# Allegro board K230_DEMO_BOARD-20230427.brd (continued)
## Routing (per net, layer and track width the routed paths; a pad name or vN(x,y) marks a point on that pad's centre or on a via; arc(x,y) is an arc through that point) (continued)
LP3_CS0: length 47.4
  TOP w0.076: v2(30.2,49.74) 29.87,50.06 U5.L3 ; v2(25.98,72.9) 25.04,73.84 U1.T20 ; R75.2 v1(31.75,46.23)
  ART03 w0.076: v2(30.2,49.74) 30.04,49.74 29.62,50.16 26.8,50.16 26.62,49.99 26.62,49.48 26.48,49.34 24.19,49.34 24.02,49.52 24.02,69.25 24.12,69.36 25.84,69.36 25.95,69.48 25.95,69.71 25.82,69.85 24.06,69.85 23.93,69.98 23.93,70.17 24.06,70.3 25.82,70.3 25.95,70.44 25.95,70.63 25.82,70.76 24.31,70.76 24.18,70.89 24.18,71.08 24.31,71.22 25.82,71.22 25.95,71.35 25.95,71.59 25.78,71.76 25.78,72.01 25.95,72.18 25.95,72.87 v2(25.98,72.9)
  ART06 w0.076: v1(31.75,46.23) 31.75,47.24 30.52,48.47 30.52,49.41 v2(30.2,49.74)
  BOTTOM w0.076: R75.2 v1(31.75,46.23)
LP3_DM0: length 32.1
  TOP w0.076: v2(32.47,74.81) 32.48,74.81 U1.D18 ; U5.L8 30.2,53.82 v2(30.2,53.74)
  ART06 w0.076: v2(32.47,74.81) 32.18,75.11 30.92,75.11 30.85,75.03 30.85,73.61 31.09,73.37 31.09,73.15 30.85,72.91 30.85,72.69 31.09,72.45 31.09,72.03 30.96,71.91 30.51,71.91 30.31,71.72 30.31,67.6 30.44,67.48 31.44,67.48 31.57,67.35 31.57,67.16 31.44,67.02 30.72,67.02 30.61,66.92 30.61,62.42 30.4,62.22 30.4,62.08 30.61,61.87 30.61,61.59 30.48,61.47 29.92,61.47 29.84,61.39 29.84,60.6 30.07,60.38 30.07,60.15 29.24,59.31 29.24,55.09 29.35,54.98 29.67,54.98 29.77,54.87 29.77,54.62 29.67,54.52 29.35,54.52 29.22,54.39 29.22,52.58 29.3,52.5 29.77,52.5 29.87,52.6 29.87,53.09 30.2,53.42 v2(30.2,53.74)
LP3_DM1: length 34.1
  TOP w0.076: v2(27.6,53.74) 27.28,54.07 U5.G8 ; U1.P17 v2(26.63,75.46)
  ART06 w0.076: v2(27.6,53.74) 27.35,53.74 27.25,53.65 27.25,52.44 27.15,52.34 26.81,52.34 26.72,52.43 26.72,54.03 26.85,54.15 27.13,54.15 27.28,54.3 27.28,59.53 27.32,59.58 27.32,62.24 28.37,63.3 28.37,65.96 28.3,66.04 26.85,66.04 26.77,66.12 26.77,71.07 26.67,71.17 26.24,71.17 26.14,71.28 26.14,72.49 26.3,72.66 26.3,73.75 26.38,73.83 27.66,73.83 27.74,73.75 27.74,73.3 27.84,73.2 28.09,73.2 28.19,73.3 28.19,74.96 28.07,75.08 27.83,75.08 27.7,74.95 27.7,74.71 27.57,74.57 27.38,74.57 27.24,74.71 27.24,75.04 26.83,75.46 v2(26.63,75.46)
LP3_DM2: length 38.6
  TOP w0.076: v2(32.15,54.54) 31.82,54.22 U5.P8 ; U1.C15 v2(33.77,76.76)
  ART06 w0.076: v2(33.77,76.76) 33.77,76.95 33.91,77.09 35.69,77.09 36.3,76.48 37.9,76.48 44.65,69.72 44.65,67.79 45.31,67.13 45.31,64.88 43.56,63.13 43.43,63.13 43.26,63.3 43.05,63.3 42.93,63.17 42.93,62.99 43.11,62.81 43.11,62.68 35.79,55.36 34.33,55.36 33.93,54.97 32.31,54.97 32.15,54.81 v2(32.15,54.54)
LP3_DM3: length 38.4
  TOP w0.076: U1.V17 v2(23.38,75.46) ; U5.D8 25.33,54.06 v2(25,53.74)
  ART06 w0.076: v2(25,53.74) 25,53.52 24.92,53.44 24.72,53.44 24.66,53.5 24.66,54.86 24.59,54.94 23.11,54.94 22.76,55.3 22.25,55.3 22.17,55.37 22.17,55.54 22.04,55.68 21.85,55.68 21.71,55.54 21.71,55.39 21.62,55.3 21.3,55.3 13.81,62.79 13.81,62.98 13.88,63.05 13.88,63.21 13.72,63.37 13.56,63.37 13.48,63.3 13.29,63.3 11.84,64.76 11.84,67.22 13.43,68.82 13.78,68.82 13.93,68.97 13.93,69.31 19.11,74.5 20.4,74.5 21.36,75.46 v2(23.38,75.46)
LP3_DQ0: length 33.3
  TOP w0.076: U5.P9 31.5,54.62 v2(31.5,54.54) ; U1.C17 v2(33.77,75.46)
  ART06 w0.076: v2(31.5,54.54) 31.17,54.21 31.17,52.66 31.27,52.56 32.52,52.56 32.61,52.65 32.61,53.21 32.49,53.34 31.9,53.34 31.82,53.42 31.82,56.44 32.72,57.33 33.02,57.33 33.15,57.45 33.15,58.29 33.83,58.98 35.37,58.98 36.14,59.75 36.14,65.76 37.06,66.67 37.06,70.03 36.22,70.87 36.22,73.76 35.93,74.05 35.93,74.41 34.88,75.46 v2(33.77,75.46)
LP3_DQ1: length 33.8
  TOP w0.076: v2(30.85,55.34) 30.85,55.27 U5.N9 ; U1.D16 v2(32.47,76.11)
  ART06 w0.076: v2(32.47,76.11) 32.7,76.11 32.8,76.01 32.8,74.63 32.66,74.49 32.25,74.49 32,74.73 31.6,74.73 31.5,74.63 31.5,71.6 31.39,71.5 30.78,71.5 30.66,71.37 30.66,70.74 30.73,70.66 31.8,70.66 31.93,70.53 31.93,70.33 31.8,70.2 30.73,70.2 30.65,70.11 30.65,69.8 30.77,69.67 31.24,69.67 31.37,69.54 31.37,69.34 31.24,69.21 30.77,69.21 30.65,69.09 30.65,68.88 30.77,68.76 31.24,68.76 31.37,68.63 31.37,68.43 31.24,68.3 30.78,68.3 30.66,68.17 30.66,67.94 30.78,67.82 31.57,67.82 31.9,67.49 31.9,66.8 31.78,66.67 31.09,66.67 30.94,66.52 30.94,61.21 30.84,61.12 30.25,61.12 30.18,61.04 30.18,60.74 30.25,60.66 30.71,60.66 30.78,60.59 30.78,60.25 29.87,59.34 29.87,55.98 30.11,55.74 30.11,54.97 30.24,54.84 30.43,54.84 30.57,54.97 30.57,55.21 30.7,55.34 v2(30.85,55.34)
LP3_DQ2: length 33.1
  TOP w0.076: U5.N10 31.17,55.67 v2(31.5,55.34) ; U1.D17 v2(33.12,76.11)
  ART06 w0.076: v2(33.12,76.11) 33.12,75.33 33.33,75.13 34.8,75.13 35.65,74.28 35.65,73.98 35.89,73.74 35.89,70.69 36.73,69.85 36.73,69.58 36.6,69.46 36.07,69.46 35.94,69.33 35.94,69.13 36.07,69 36.6,69 36.73,68.87 36.73,68.67 36.6,68.54 35.89,68.54 35.79,68.44 35.79,68.19 35.89,68.09 36.6,68.09 36.73,67.96 36.73,67.76 36.6,67.63 35.92,67.63 35.81,67.53 35.81,67.27 35.92,67.17 36.6,67.17 36.73,67.04 36.73,66.83 36.63,66.73 35.92,66.73 35.81,66.63 35.81,59.89 35.23,59.31 34.16,59.31 34.04,59.44 34.04,59.69 33.92,59.8 33.68,59.8 33.58,59.7 33.58,59.44 33.45,59.31 33.1,59.31 32.47,58.69 32.47,57.45 31.5,56.48 v2(31.5,55.34)
LP3_DQ3: length 31.9
  TOP w0.076: U1.C18 33.13,74.81 v2(33.12,74.81) ; v2(31.5,56.94) 31.5,56.87 U5.N11
  ART06 w0.076: v2(31.5,56.94) 31.5,57.2 32.14,57.85 32.14,58.85 33.46,60.17 34.34,60.17 34.42,60.1 34.42,59.72 34.49,59.64 34.8,59.64 34.87,59.72 34.87,60.09 34.95,60.17 35.38,60.17 35.46,60.25 35.46,61.45 35.38,61.53 34.01,61.53 33.88,61.65 33.88,61.86 34.01,61.98 35.33,61.98 35.46,62.11 35.46,62.31 35.33,62.44 34,62.44 33.88,62.56 33.88,62.87 33.99,62.97 35.38,62.97 35.46,63.04 35.46,63.32 35.32,63.45 34.98,63.45 34.9,63.53 34.9,63.83 34.98,63.91 35.32,63.91 35.46,64.04 35.46,68.66 35.56,68.76 35.56,69.62 35.69,69.76 35.88,69.76 36.02,69.89 36.02,70.08 35.88,70.21 35.69,70.21 35.56,70.35 35.56,73.69 35.28,73.96 35.28,74.23 35.01,74.5 33.2,74.5 33.12,74.57 v2(33.12,74.81)
LP3_DQ4: length 33.8
  TOP w0.076: U1.E18 v2(32.47,75.46) ; U5.M8 30.52,53.51 30.35,53.34 28.65,53.34 v2(28.25,52.94)
  ART06 w0.076: v2(32.47,75.46) 32.47,75.68 32.37,75.79 30.96,75.79 30.86,75.89 30.86,76.66 30.76,76.76 29.72,76.76 29.62,76.66 29.62,76.42 29.75,76.28 30.02,76.28 30.15,76.15 30.15,75.96 30.02,75.83 29.8,75.83 29.67,75.69 29.67,73.48 30.18,72.97 30.18,72.64 29.65,72.12 29.65,67.2 29.95,66.9 29.95,62.7 29.17,61.93 29.17,60.06 28.7,59.59 28.7,55.96 28.5,55.75 28.07,55.75 27.93,55.61 27.93,53.58 28.25,53.26 v2(28.25,52.94)
LP3_DQ5: length 33
  TOP w0.076: v2(30.85,54.54) 30.52,54.87 U5.M9 ; U1.E17 v2(31.82,75.46)
  ART06 w0.076: v2(30.85,54.54) 30.64,54.54 30.53,54.43 30.53,51.82 30.45,51.74 28.68,51.74 28.57,51.84 28.57,55.24 28.97,55.64 28.97,59.42 29.51,59.97 29.51,61.8 30.28,62.56 30.28,67.06 29.98,67.35 29.98,71.95 30.53,72.49 30.53,73.46 30.43,73.56 30.2,73.56 30.02,73.74 30.02,74.22 30.35,74.55 30.35,74.73 30.02,75.06 30.02,75.36 30.12,75.46 v2(31.82,75.46)
LP3_DQ6: length 30.5
  TOP w0.076: v2(30.85,56.14) 30.85,56.07 U5.M10 ; U1.B19 v2(34.42,74.16)
  ART06 w0.076: v2(30.85,56.14) 31.1,56.14 31.17,56.22 31.17,58 31.32,58.14 31.74,58.14 31.81,58.22 31.81,58.98 32.82,59.98 32.82,60.43 32.9,60.51 35.01,60.51 35.13,60.63 35.13,60.86 35,60.99 32.92,60.99 32.82,61.09 32.82,61.34 32.92,61.44 33.45,61.44 33.55,61.54 33.55,61.85 33.4,62 33.4,62.26 33.55,62.41 33.55,63.2 33.68,63.33 34.47,63.33 34.57,63.43 34.57,63.68 34.29,63.96 34.01,63.96 33.84,63.78 33.62,63.78 33.5,63.91 33.5,64.72 33.6,64.82 34.44,64.82 34.54,64.72 34.54,64.36 34.65,64.26 35.03,64.26 35.13,64.36 35.13,68.81 35.23,68.91 35.23,73.56 35,73.79 35,74.09 34.87,74.22 34.48,74.22 v2(34.42,74.16)
LP3_DQ7: length 30.7
  TOP w0.076: U5.M11 30.85,56.87 v2(30.85,56.94) ; U1.C19 v2(33.77,74.16)
  ART06 w0.076: v2(30.85,56.94) 30.85,58.49 32.49,60.12 32.49,62.36 32.61,62.49 33.07,62.49 33.2,62.61 33.2,62.82 33.07,62.94 32.61,62.94 32.49,63.07 32.49,63.27 32.61,63.4 33.07,63.4 33.2,63.53 33.2,63.73 33.07,63.86 32.61,63.86 32.49,63.99 32.49,65 32.64,65.15 34.7,65.15 34.8,65.25 34.8,65.45 34.7,65.55 33.94,65.55 33.86,65.63 33.86,68.43 33.99,68.55 34.19,68.55 34.32,68.43 34.32,66.13 34.45,66.01 34.71,66.01 34.8,66.09 34.8,69.16 34.9,69.27 34.9,73.53 34.59,73.84 34.1,73.84 v2(33.77,74.16)
LP3_DQ8: length 33.6
  TOP w0.076: U5.F11 26.95,56.87 v2(26.95,57.74) ; U1.R18 v2(25.98,75.46)
  ART06 w0.076: v2(25.98,75.46) 25.98,74.72 25.65,74.39 25.65,72.62 25.7,72.57 25.7,70.94 25.83,70.82 26.31,70.82 26.44,70.69 26.44,70.48 26.34,70.38 25.83,70.38 25.7,70.26 25.7,70.05 25.83,69.93 26.31,69.93 26.42,69.82 26.42,69.57 26.31,69.47 25.83,69.47 25.7,69.34 25.7,69.14 25.83,69.01 26.29,69.01 26.42,68.89 26.42,68.68 26.29,68.55 25.81,68.55 25.7,68.45 25.7,68.2 25.81,68.09 26.29,68.09 26.42,67.97 26.42,65.8 26.55,65.67 27.91,65.67 28.04,65.54 28.04,65.35 27.91,65.21 26.52,65.21 26.39,65.08 26.39,64.89 26.52,64.75 27.91,64.75 28.04,64.62 28.04,64.43 27.91,64.3 26.55,64.3 26.42,64.16 26.42,63.9 26.57,63.75 27.84,63.75 27.97,63.62 27.97,63.42 27.84,63.29 26.31,63.29 26.19,63.17 26.19,62.89 26.29,62.79 27.07,62.79 27.15,62.71 27.15,62.55 26.95,62.36 v2(26.95,57.74)
LP3_DQ9: length 36.2
  TOP w0.076: v2(25.98,76.11) U1.P16 ; U5.F10 26.63,55.82 v2(26.95,56.14)
  ART06 w0.076: v2(25.98,76.11) U1.P16 28.17,76.44 28.27,76.54 28.27,77.01 28.19,77.09 25.8,77.09 25.65,76.93 25.65,74.88 25.36,74.59 25.36,67.88 25.49,67.75 25.96,67.75 26.09,67.62 26.09,65.56 25.98,65.46 25.49,65.46 25.36,65.34 25.36,65.15 25.5,65.02 25.93,65.02 26.06,64.89 26.06,64.7 25.93,64.56 25.5,64.56 25.36,64.43 25.36,64.24 25.5,64.11 25.93,64.11 26.06,63.97 26.06,63.78 25.93,63.65 25.5,63.65 25.36,63.51 25.36,63.34 25.5,63.21 25.7,63.21 25.83,63.07 25.83,62.36 25.91,62.28 26.51,62.28 26.62,62.18 26.62,61.9 26.49,61.77 24.51,61.77 24.38,61.65 24.38,61.44 24.51,61.32 26.49,61.32 26.62,61.19 26.62,57.45 26.95,57.12 v2(26.95,56.14)
LP3_DQ10: length 34.2
  TOP w0.076: U1.R17 v2(25.33,75.46) ; U5.F9 26.95,54.62 v2(26.95,54.54)
  ART06 w0.076: v2(26.95,54.54) 26.63,54.87 26.63,56.94 26.29,57.28 26.29,59.97 26.19,60.07 24.31,60.07 24.21,60.17 24.21,60.43 24.31,60.53 26.21,60.53 26.29,60.61 26.29,60.9 26.21,60.97 24.14,60.97 24.05,61.06 24.05,62 24.16,62.11 25.36,62.11 25.48,62.23 25.48,62.42 25.34,62.57 24.15,62.57 24.05,62.66 24.05,62.91 24.13,62.99 24.89,62.99 25.03,63.12 25.03,65.79 25.16,65.93 25.62,65.93 25.76,66.06 25.76,66.25 25.62,66.38 25.16,66.38 25.03,66.52 25.03,66.71 25.16,66.84 25.62,66.84 25.76,66.97 25.76,67.16 25.62,67.3 25.21,67.3 25.03,67.48 25.03,75.36 25.13,75.46 v2(25.33,75.46)
LP3_DQ11: length 31.4
  TOP w0.076: v2(23.05,72.64) 22.73,72.97 22.73,74.16 U1.W19 ; v2(26.3,53.74) 26.3,53.82 U5.F8
  ART06 w0.076: v2(26.3,53.74) 26.39,53.65 26.39,53.39 26.29,53.29 25.45,53.29 25.37,53.37 25.37,54.05 25.46,54.14 25.87,54.14 25.98,54.25 25.98,54.75 25.65,55.07 25.65,56.52 24.51,57.66 24.51,57.87 22.71,59.68 22.71,61.93 22.58,62.05 21.67,62.05 21.54,62.18 21.54,63.87 21.62,63.95 21.92,63.95 22.02,64.05 22.02,64.33 21.95,64.41 21.62,64.41 21.54,64.48 21.54,64.89 21.67,65.02 21.94,65.02 22.07,65.15 22.07,65.34 21.94,65.48 21.67,65.48 21.54,65.61 21.54,65.95 21.62,66.03 22.66,66.03 22.73,66.11 22.73,66.41 22.66,66.49 21.67,66.49 21.54,66.62 21.54,69.37 21.69,69.52 21.69,69.67 21.54,69.82 21.54,70 21.64,70.1 22.58,70.1 22.67,70.19 22.67,72.5 22.81,72.64 v2(23.05,72.64)
LP3_DQ12: length 32.4
  TOP w0.076: U1.T18 v2(24.68,74.81) ; v2(25.65,57.74) 25.65,56.87 U5.E11
  ART06 w0.076: v2(25.65,57.74) 25.65,58.04 25.33,58.37 25.33,59.33 25.25,59.41 25.01,59.41 24.87,59.28 24.87,59.06 24.74,58.93 24.55,58.93 24.42,59.06 24.42,59.28 24.28,59.41 23.95,59.41 23.39,59.97 23.39,62.69 23.26,62.82 22.3,62.82 22.2,62.92 22.2,63.17 22.3,63.27 23.27,63.27 23.39,63.4 23.39,67.06 23.29,67.16 22.33,67.16 22.23,67.26 22.23,67.52 22.35,67.65 23.42,67.65 23.52,67.75 23.52,68 23.42,68.1 22.35,68.1 22.23,68.23 22.23,68.45 22.34,68.57 22.98,68.57 23.09,68.68 23.09,69.06 23.22,69.19 24.26,69.19 24.36,69.29 24.36,69.54 24.25,69.65 23.48,69.65 23.34,69.78 23.34,69.99 23.47,70.12 24.27,70.12 24.36,70.2 24.36,70.5 24.28,70.58 23.46,70.58 23.33,70.7 23.33,70.91 23.46,71.03 24.21,71.03 24.35,71.18 24.35,74.69 24.47,74.81 v2(24.68,74.81)
LP3_DQ13: length 32.6
  TOP w0.076: U5.E10 26.3,55.42 v2(26.3,55.34) ; U1.U20 v2(24.68,73.51)
  ART06 w0.076: v2(26.3,55.34) 26.3,56.81 25.97,57.14 25.97,58.78 25.73,59.02 25.73,59.24 25.97,59.48 25.97,59.66 25.9,59.74 24.18,59.74 23.72,60.2 23.72,63.23 23.86,63.36 24.61,63.36 24.69,63.44 24.69,63.74 24.61,63.82 23.86,63.82 23.72,63.95 23.72,64.11 23.85,64.24 24.61,64.24 24.69,64.32 24.69,64.62 24.61,64.7 23.85,64.7 23.72,64.83 23.72,65.03 23.85,65.16 24.59,65.16 24.69,65.25 24.69,65.53 24.61,65.61 23.85,65.61 23.72,65.74 23.72,65.94 23.85,66.07 24.56,66.07 24.69,66.2 24.69,66.4 24.56,66.53 23.85,66.53 23.72,66.65 23.72,66.86 23.85,66.98 24.61,66.98 24.71,67.09 24.71,67.34 24.61,67.44 23.98,67.44 23.85,67.57 23.85,67.77 23.98,67.9 24.61,67.9 24.69,67.97 24.69,68.31 24.61,68.38 23.6,68.38 23.47,68.52 23.47,68.71 23.6,68.84 24.55,68.84 24.69,68.97 24.69,73.5 v2(24.68,73.51)
LP3_DQ14: length 33.2
  TOP w0.076: v2(26.3,54.54) 26.3,54.62 U5.E9 ; U1.U18 v2(24.03,74.81)
  ART06 w0.076: v2(26.3,54.54) 26.3,54.88 25.97,55.21 25.97,56.71 25.33,57.35 25.33,57.87 25.03,58.17 24.71,58.17 23.06,59.82 23.06,62.39 22.99,62.47 22,62.47 21.87,62.6 21.87,63.45 22.02,63.6 22.99,63.6 23.06,63.68 23.06,63.99 22.99,64.07 22.44,64.07 22.35,64.16 22.35,64.45 22.43,64.53 22.99,64.53 23.06,64.6 23.06,64.97 22.99,65.04 22.73,65.04 22.61,65.17 22.61,65.37 22.73,65.5 22.99,65.5 23.06,65.58 23.06,66.75 22.99,66.83 21.97,66.83 21.89,66.9 21.89,69.24 22,69.34 22.89,69.34 23,69.46 23,69.58 22.86,69.72 22.86,69.9 23,70.04 23,71.32 23.08,71.4 23.92,71.4 24.02,71.49 24.02,71.74 23.9,71.85 23.09,71.85 23.01,71.93 23.01,72.21 23.09,72.29 23.95,72.29 24.03,72.36 24.03,72.66 23.94,72.75 23.5,72.75 23.37,72.87 23.37,73.1 23.5,73.24 23.87,73.24 24,73.37 24,73.56 23.87,73.7 23.67,73.7 23.6,73.77 23.6,74.19 24.03,74.62 v2(24.03,74.81)
LP3_DQ15: length 33.6
  TOP w0.076: U1.T17 v2(24.68,75.46) ; U5.D9 25.33,54.87 v2(25,54.54)
  ART06 w0.076: v2(24.68,75.46) 24.68,75.25 24.56,75.14 23.89,75.14 23.7,74.94 23.7,74.69 23.32,74.31 23.32,74.12 22.72,73.52 22.72,73.13 22.62,73.03 22.42,73.03 22.34,72.95 22.34,71.46 22.08,71.2 22.08,71.01 22.33,70.76 22.33,70.57 22.2,70.44 22.01,70.44 21.76,70.69 21.57,70.69 21.21,70.33 21.21,63.37 21.08,63.24 20.91,63.24 20.78,63.1 20.78,62.92 20.91,62.78 21.08,62.78 21.21,62.65 21.21,61.82 21.34,61.69 22.07,61.69 22.2,61.56 22.2,61.37 22.07,61.23 21.34,61.23 21.21,61.1 21.21,60.9 21.34,60.77 22.27,60.77 22.4,60.63 22.4,60.44 22.27,60.31 21.34,60.31 21.21,60.17 21.21,59.94 21.31,59.84 22.28,59.84 22.36,59.75 22.36,59.46 22.26,59.36 21.74,59.36 21.64,59.26 21.64,59.03 21.77,58.9 22.99,58.9 23.17,58.72 23.17,58.31 23.39,58.09 23.8,58.09 24.13,57.76 24.13,57.66 25.34,56.45 25.34,54.54 25.26,54.46 25.08,54.46 v2(25,54.54)
LP3_DQ16: length 40.2
  TOP w0.076: v2(33.78,78.06) 33.77,78.06 U1.C14 ; v2(33.45,53.74) 33.12,54.06 U5.T8
  ART06 w0.076: v2(33.78,78.06) 38.2,78.06 46.63,69.62 46.63,64.33 36.05,53.74 v2(33.45,53.74)
LP3_DQ17: length 38.6
  TOP w0.076: U5.T9 33.58,54.48 35.23,54.48 v2(35.69,54.94) ; U1.B14 v2(33.78,77.41)
  ART06 w0.076: v2(35.69,54.94) 35.84,54.94 45.64,64.74 45.64,67.31 45.36,67.59 45.36,67.8 45.64,68.08 45.64,68.25 45.57,68.32 45.06,68.32 44.98,68.4 44.98,68.68 45.06,68.75 45.56,68.75 45.64,68.83 45.64,69.2 38.06,76.78 36.37,76.78 36.07,77.09 36.07,77.29 35.95,77.41 v2(33.78,77.41)
LP3_DQ18: length 38.7
  TOP w0.076: U1.C16 v2(33.13,76.76) ; v2(35.65,55.75) 35.24,55.34 33.52,55.34 U5.T10
  ART06 w0.076: v2(33.13,76.76) U1.C16 33.92,76.44 34.25,76.77 35.63,76.77 36.23,76.17 37.73,76.17 43.76,70.14 43.76,68.91 43.61,68.75 41.45,68.75 39.83,67.13 39.83,64.88 41.47,63.25 42.34,63.25 42.44,63.14 42.44,62.48 35.71,55.75 v2(35.65,55.75)
LP3_DQ19: length 38.1
  TOP w0.076: v2(35.58,75.46) 35.26,75.79 U1.A17 ; v2(34.92,57.28) 34.59,56.94 33.52,56.94 U5.T11
  ART06 w0.076: v2(35.58,75.46) 35.58,75.29 35.67,75.2 37.3,75.2 38.42,74.08 38.42,73.9 38.14,73.62 38.14,73.44 38.28,73.3 38.46,73.3 38.74,73.58 38.92,73.58 39.95,72.54 39.95,71.88 40.06,71.78 40.72,71.78 40.84,71.65 40.84,71.45 40.72,71.32 39.71,71.32 39.59,71.19 39.59,70.99 39.71,70.86 40.77,70.86 40.89,70.74 40.89,70.53 40.77,70.4 40.11,70.4 39.98,70.28 39.98,70.07 40.11,69.95 40.77,69.95 40.89,69.82 40.89,69.62 40.77,69.49 40.26,69.49 40.13,69.36 40.13,68.85 39.99,68.71 39.78,68.71 39.55,68.48 39.55,68.26 39.42,68.13 39.24,68.13 38.97,68.41 38.79,68.41 38.65,68.26 38.65,68.08 38.92,67.81 38.92,67.63 38.68,67.4 38.68,64.59 38.83,64.45 38.83,64.26 38.69,64.12 38.69,63.93 38.82,63.79 39.01,63.79 39.15,63.93 39.34,63.93 40.26,63.02 40.26,61.71 39.76,61.21 39.2,61.21 39.07,61.08 39.07,60.54 38.93,60.4 38.75,60.4 38.61,60.54 38.61,61.08 38.48,61.21 38.25,61.21 38.13,61.09 38.13,59.58 35.83,57.28 v2(34.92,57.28)
LP3_DQ20: length 40.7
  TOP w0.076: U1.D14 v2(33.13,77.41) ; v2(32.8,53.74) 32.47,54.06 U5.R8
  ART06 w0.076: v2(32.8,53.74) 33.16,54.1 35.94,54.1 46.3,64.47 46.3,69.48 38.05,77.74 33.45,77.74 v2(33.13,77.41)
LP3_DQ21: length 37.5
  TOP w0.076: U5.R9 32.8,54.62 v2(32.8,54.54) ; U1.A14 36.97,77.74 37.59,77.11 v2(37.77,77.11)
  ART06 w0.076: v2(32.8,54.54) 32.88,54.46 34.65,54.46 34.77,54.58 35.15,54.58 35.28,54.46 35.83,54.46 45.97,64.6 45.97,69.34 38.2,77.11 v2(37.77,77.11)
LP3_DQ22: length 37.7
  TOP w0.076: v2(32.8,55.34) 32.47,55.67 U5.R10 ; U1.B17 v2(33.77,76.11)
  ART06 w0.076: v2(32.8,55.34) 33.78,55.34 34.06,55.63 34.06,55.96 34.24,56.13 35.62,56.13 42.11,62.62 42.11,62.84 42.04,62.92 41.33,62.92 39.5,64.74 39.5,67.27 41.31,69.09 43.33,69.09 43.43,69.19 43.43,70 37.57,75.87 36.05,75.87 35.81,76.1 35.03,76.1 34.67,76.45 34.29,76.45 33.95,76.11 v2(33.77,76.11)
LP3_DQ23: length 38.7
  TOP w0.076: U5.R11 32.88,56.13 35.09,56.13 v2(35.73,56.77) ; U1.B16 v2(34.42,76.11)
  ART06 w0.076: v2(34.42,76.11) 34.42,75.87 34.5,75.79 35.71,75.79 35.98,75.53 37.44,75.53 42.2,70.77 42.2,70.42 42.35,70.27 42.7,70.27 43.08,69.89 43.08,69.51 42.99,69.42 42.72,69.42 42.65,69.49 42.65,69.69 42.51,69.82 42.32,69.82 42.19,69.69 42.19,69.51 42.11,69.43 41.81,69.43 41.67,69.57 41.67,70.69 41.54,70.82 41.35,70.82 41.22,70.69 41.22,69.47 39.01,67.26 39.01,67.02 39.17,66.87 39.17,66.56 39.01,66.41 39.01,66.1 39.17,65.95 39.17,65.65 39.01,65.49 39.01,64.74 40.59,63.17 40.59,62.72 40.72,62.58 41.14,62.58 41.27,62.45 41.27,62.26 41.14,62.12 40.72,62.12 40.59,61.99 40.59,61.57 35.79,56.77 v2(35.73,56.77)
LP3_DQ24: length 37.1
  TOP w0.076: U1.W18 v2(22.73,74.81) ; v2(21.84,56.68) 22.1,56.94 24.28,56.94 U5.C11
  ART06 w0.076: v2(22.73,74.81) 22.58,74.81 22.5,74.73 22.5,74.32 22.33,74.14 21.64,74.14 21.01,73.51 19.53,73.51 16.38,70.36 16.38,70.02 16.25,69.88 15.91,69.88 15.77,69.75 15.77,69.56 15.91,69.43 16.25,69.43 16.38,69.29 16.38,69.06 17.4,68.05 17.86,68.05 17.98,67.92 17.98,62.92 17.85,62.78 17.25,62.78 17.17,62.7 17.17,61.95 17.09,61.88 16.61,61.88 16.48,61.75 16.48,61.55 16.61,61.42 19.18,61.42 19.25,61.34 19.25,61.04 19.16,60.95 17.6,60.95 17.48,60.82 17.48,60.62 17.6,60.49 18.17,60.49 18.3,60.36 18.3,59.97 18.43,59.84 18.63,59.84 18.76,59.97 18.76,60.36 18.89,60.49 19.23,60.49 19.3,60.41 19.3,58.73 21.02,57.01 21.26,57.01 21.59,56.68 v2(21.84,56.68)
LP3_DQ25: length 37.2
  TOP w0.076: v2(24.35,55.34) 24.68,55.67 U5.C10 ; U1.V18 v2(23.38,74.81)
  ART06 w0.076: v2(23.38,74.81) 23.14,74.81 23.01,74.68 23.01,74.32 22.53,73.84 21.84,73.84 21.67,73.66 21.67,73.25 21.59,73.18 20.64,73.18 20.52,73.05 20.52,72.64 20.39,72.52 20.19,72.52 20.06,72.64 20.06,73.05 19.93,73.18 19.68,73.18 17.45,70.94 17.45,70.75 17.55,70.65 17.55,70.48 17.39,70.33 17.23,70.33 17.13,70.43 16.94,70.43 16.74,70.23 16.74,69.19 17.48,68.45 18.44,68.45 18.59,68.3 18.59,68.02 18.31,67.74 18.31,63.91 18.44,63.78 18.97,63.78 19.08,63.68 19.08,63.28 19,63.21 18.39,63.21 18.31,63.13 18.31,62.83 18.39,62.75 19.01,62.75 19.1,62.66 19.1,62.37 19.02,62.29 17.58,62.29 17.5,62.22 17.5,61.93 17.59,61.84 19.51,61.84 19.63,61.71 19.63,58.88 21.17,57.34 21.4,57.34 21.72,57.02 22.07,57.02 22.23,56.87 22.23,56.24 22.38,56.08 22.66,56.08 22.81,56.24 23.04,56.24 23.26,56.01 23.26,55.83 23.08,55.66 23.08,55.48 23.23,55.33 23.41,55.33 23.65,55.58 23.83,55.58 24.06,55.34 v2(24.35,55.34)
LP3_DQ26: length 38.2
  TOP w0.076: U1.V16 v2(23.38,76.11) ; v2(24.35,54.54) 24.68,54.87 U5.C9
  ART06 w0.076: v2(24.35,54.54) 24.41,54.48 24.41,54.17 24.33,54.09 23.74,54.09 23.66,54.17 23.66,54.52 23.57,54.61 23.39,54.61 23.22,54.43 22.86,54.43 22.73,54.56 22.43,54.56 22.3,54.43 21.22,54.43 11.18,64.48 11.18,67.5 18.83,75.16 20.04,75.16 20.99,76.11 v2(23.38,76.11)
LP3_DQ27: length 36.9
  TOP w0.076: v2(24.35,53.74) 24.68,54.06 U5.C8 ; U1.Y16 21.9,76.44 21.41,75.95 v2(20.32,75.95)
  ART06 w0.076: v2(24.35,53.74) 23.25,53.74 22.9,54.09 21.09,54.09 10.85,64.34 10.85,67.64 18.77,75.56 19.94,75.56 v2(20.32,75.95)
LP3_DQ28: length 36
  TOP w0.076: U1.Y18 v2(22.08,74.81) ; v2(21.08,56.64) 21.36,56.36 22.23,56.36 22.45,56.14 23.63,56.14 U5.B11
  ART06 w0.076: v2(22.08,74.81) 22.08,74.52 22,74.45 21.46,74.45 20.85,73.84 19.39,73.84 14.94,69.38 14.94,69.16 15.02,69.08 15.89,69.08 17.65,67.31 17.65,64.12 17.57,64.04 17.05,64.04 16.94,63.93 16.94,63.69 17.05,63.58 17.57,63.58 17.65,63.5 17.65,63.22 17.57,63.14 15.8,63.14 15.67,63.01 15.67,62.81 15.8,62.68 16.69,62.68 16.81,62.56 16.81,62.33 16.7,62.21 15.7,62.21 15.62,62.14 15.62,61.92 18.23,59.31 18.44,59.31 18.63,59.5 18.81,59.5 18.95,59.36 18.95,59.18 18.76,58.99 18.76,58.78 20.9,56.64 v2(21.08,56.64)
LP3_DQ29: length 37.8
  TOP w0.076: v2(21.22,56.01) 21.89,55.34 23.63,55.34 U5.B10 ; v2(24.03,75.46) 24.35,75.78 U1.U17
  ART06 w0.076: v2(21.22,56.01) 21.05,56.01 14.99,62.08 14.99,62.26 15.08,62.35 15.29,62.35 15.37,62.43 15.37,62.66 15.25,62.78 14.36,62.78 14.25,62.89 14.25,63.12 14.35,63.22 15.39,63.22 15.67,63.5 16.54,63.5 16.61,63.58 16.61,64.17 16.81,64.37 17.2,64.37 17.32,64.5 17.32,67.14 15.72,68.75 14.44,68.75 14.33,68.86 14.33,69.24 19.25,74.17 20.65,74.17 21.62,75.14 23.56,75.14 23.89,75.46 v2(24.03,75.46)
LP3_DQ30: length 38.9
  TOP w0.076: v2(21.36,54.89) 21.71,54.54 23.63,54.54 U5.B9 ; U1.T16 v2(25.33,76.11)
  ART06 w0.076: v2(21.36,54.89) 21.23,54.89 11.51,64.62 11.51,67.36 18.97,74.83 20.22,74.83 21.18,75.79 24.26,75.79 24.39,75.91 24.39,76.45 24.52,76.58 24.72,76.58 24.85,76.45 24.85,75.91 24.98,75.79 25.16,75.79 25.33,75.95 v2(25.33,76.11)
LP3_DQ31: length 39.6
  TOP w0.076: U5.B8 23.2,53.31 21.64,53.31 v2(21.23,53.72) ; U1.U16 v2(24.03,76.11)
  ART06 w0.076: v2(21.23,53.72) 20.99,53.72 10.52,64.2 10.52,67.79 19.08,76.35 20.17,76.35 20.25,76.43 23.7,76.43 v2(24.03,76.11)
LP3_DQS0_C: length 30.9
  TOP w0.089: U5.L11 30.2,56.87 v2(30.2,56.94) ; v2(34.42,72.86) 34.42,72.64 34.56,72.5 34.78,72.5 34.88,72.6 34.88,72.75 34.8,72.83 34.8,72.97 34.9,73.08 35.05,73.08 35.13,73 35.28,73 35.45,73.16 35.45,73.29 35.34,73.39 35.16,73.39 35.05,73.49 35.05,73.64 35.16,73.75 35.34,73.75 35.45,73.85 35.45,74 35.34,74.1 35.18,74.1 35.08,74.21 35.08,74.35 35.18,74.46 35.34,74.46 35.45,74.56 35.45,74.66 34.95,75.16 34.77,75.16 U1.A18
  ART06 w0.089: v2(34.42,72.86) 34.42,72.65 34.33,72.55 33.75,72.55 33.63,72.67 33.63,73.34 33.19,73.77 32.42,73.77 32.02,73.37 32.02,71.72 32.46,71.27 33.5,71.27 33.78,70.99 33.78,70.08 33.56,69.86 32.34,69.86 31.97,69.48 31.97,68.57 32.91,67.63 32.91,66.25 32.75,66.09 31.92,66.09 31.53,65.7 31.53,60.34 30.19,58.99 30.19,56.95 v2(30.2,56.94)
LP3_DQS0_T: length 31.1
  TOP w0.089: v2(34.42,72.21) 34.9,72.21 35.74,73.04 35.74,74.78 35.07,75.45 34.42,75.45 U1.B18 ; U5.L10 30.2,56.07 v2(30.2,56.14)
  ART06 w0.089: v2(30.2,56.14) 30.53,56.47 30.53,58.85 31.88,60.2 31.88,65.56 32.07,65.75 32.89,65.75 33.25,66.1 33.25,67.77 32.31,68.71 32.31,69.34 32.49,69.52 33.71,69.52 34.12,69.94 34.12,71.13 33.64,71.62 32.6,71.62 32.36,71.86 32.36,73.23 32.57,73.43 33.05,73.43 33.29,73.2 33.29,72.53 33.6,72.21 v2(34.42,72.21)
LP3_DQS1_C: length 31.4
  TOP w0.089: v2(26.63,72.21) 26.61,72.22 24.67,72.22 23.39,73.5 23.39,74.18 U1.V19 ; U5.G11 27.28,56.62 v2(27.6,56.94)
  ART06 w0.089: v2(26.63,72.21) 26.63,72.43 26.71,72.52 27.2,72.52 27.7,72.02 28.56,72.02 28.71,71.87 28.71,71.53 28.56,71.37 27.74,71.37 27.38,71.01 27.38,70.51 27.74,70.15 28.56,70.15 28.71,70 28.71,69.77 28.56,69.62 27.74,69.62 27.38,69.26 27.38,68.76 27.74,68.4 28.56,68.4 28.71,68.24 28.71,68.02 28.56,67.87 27.81,67.87 27.46,67.51 27.46,67 27.81,66.65 28.81,66.65 28.97,66.49 28.97,63.06 28.04,62.13 28.04,61.93 28.23,61.73 28.23,61.21 28.13,61.11 28.02,61.11 27.91,61 27.91,60.83 28.02,60.73 28.13,60.73 28.23,60.62 28.23,60.37 27.84,59.97 27.76,59.97 27.66,59.87 27.66,59.72 27.76,59.61 27.84,59.61 27.94,59.51 27.94,57.45 28.04,57.35 28.04,56.87 27.81,56.64 27.69,56.64 27.6,56.73 v2(27.6,56.94)
LP3_DQS1_T: length 31.3
  TOP w0.089: U5.G10 27.28,55.82 v2(27.6,56.14) ; v2(26.63,72.86) 26.63,72.67 26.48,72.52 25.64,72.52 25.54,72.62 25.54,72.79 25.43,72.9 25.28,72.9 25.18,72.79 25.18,72.62 25.08,72.52 24.79,72.52 24.69,72.62 24.69,72.77 24.81,72.89 24.81,73.03 24.7,73.14 24.56,73.14 24.44,73.02 24.29,73.02 23.7,73.61 U1.V20
  ART06 w0.089: v2(26.63,72.86) 27.35,72.86 27.84,72.36 28.7,72.36 29.06,72.01 29.06,71.38 28.7,71.03 27.88,71.03 27.72,70.87 27.72,70.65 27.88,70.49 28.7,70.49 29.06,70.14 29.06,69.63 28.7,69.28 27.88,69.28 27.72,69.12 27.72,68.9 27.88,68.74 28.7,68.74 29.06,68.38 29.06,67.88 28.7,67.52 27.96,67.52 27.8,67.37 27.8,67.15 27.96,66.99 28.95,66.99 29.31,66.63 29.31,62.92 28.57,62.18 28.57,60.22 28.28,59.93 28.28,57.59 28.39,57.49 28.39,56.73 27.95,56.3 27.76,56.3 v2(27.6,56.14)
LP3_DQS2_C: length 38.4
  TOP w0.089: U5.P11 32.15,56.22 v2(32.15,56.14) ; U1.A15 34.78,77.11 35.41,77.11 35.92,76.61 35.92,76.46 35.78,76.33 35.78,76.18 35.89,76.07 36.04,76.07 36.17,76.21 36.32,76.21 36.42,76.1 36.42,75.96 36.31,75.85 36.31,75.7 36.42,75.6 36.56,75.6 36.67,75.7 36.82,75.7 36.88,75.64 36.88,74.98 36.68,74.78 v2(36.53,74.78)
  ART06 w0.089: v2(36.53,74.78) 36.69,74.62 36.69,73.95 36.92,73.72 36.92,72.62 37.22,72.32 38.85,72.32 39,72.16 39,71.94 38.85,71.78 37.33,71.78 37.02,71.48 37.02,70.9 37.67,70.25 37.67,65.94 37.55,65.82 37.11,65.82 36.75,65.46 36.75,64.96 37.11,64.6 37.61,64.6 37.74,64.47 37.74,64.25 37.56,64.07 37.16,64.07 36.8,63.71 36.8,63.2 37.16,62.85 39.11,62.85 39.29,62.66 39.29,62.36 39.11,62.17 37.13,62.17 36.75,61.8 36.75,61.14 37.19,60.7 37.19,59.96 35.61,58.38 34.2,58.38 33.69,57.87 33.69,56.73 33.51,56.55 33.36,56.55 33.3,56.6 33.16,56.6 33.05,56.5 33.05,56.35 33.11,56.29 33.11,56.15 32.97,56.01 32.28,56.01 v2(32.15,56.14)
LP3_DQS2_T: length 38.7
  TOP w0.089: v2(37.17,74.78) 37.17,75.76 35.53,77.4 34.42,77.4 34.28,77.26 U1.B15 ; U5.P10 32.15,55.42 v2(32.15,55.34)
  ART06 w0.089: v2(37.17,74.78) 37.03,74.64 37.03,74.09 37.26,73.86 37.26,72.77 37.37,72.66 38.99,72.66 39.34,72.3 39.34,71.8 38.99,71.44 37.47,71.44 37.36,71.33 37.36,71.04 38.01,70.4 38.01,65.8 37.69,65.48 37.25,65.48 37.1,65.32 37.1,65.1 37.25,64.94 37.76,64.94 38.09,64.61 38.09,64.11 37.71,63.72 37.3,63.72 37.15,63.57 37.15,63.35 37.3,63.19 39.25,63.19 39.64,62.8 39.64,62.21 39.25,61.83 37.27,61.83 37.1,61.66 37.1,61.28 37.53,60.85 37.53,59.81 35.75,58.04 34.34,58.04 34.04,57.73 34.04,56.59 33.11,55.66 32.47,55.66 v2(32.15,55.34)
LP3_DQS3_C: length 36.4
  TOP w0.089: v2(21.72,72.52) 21.49,72.52 21.36,72.65 21.36,74.29 21.46,74.39 21.61,74.39 21.72,74.5 21.72,74.64 21.61,74.75 21.46,74.75 21.36,74.85 21.36,75.08 21.63,75.35 21.78,75.35 21.9,75.23 22.04,75.23 22.15,75.34 22.15,75.48 22.03,75.6 22.03,75.75 22.08,75.8 22.39,75.8 U1.Y17 ; v2(25,56.14) 25,56.22 U5.D11
  ART06 w0.089: v2(21.72,72.52) 21.56,72.52 21.48,72.43 21.48,71.46 21.08,71.07 20.47,71.07 19.96,71.58 19.41,71.58 18.85,71.02 18.85,70.74 19.1,70.49 20.27,70.49 20.62,70.14 20.62,69.61 20.27,69.27 19.59,69.27 19.46,69.14 19.46,68.89 19.61,68.73 20.3,68.73 20.62,68.41 20.62,67.76 20.3,67.44 19.38,67.44 19.26,67.32 19.26,66.92 19.38,66.81 20.32,66.81 20.62,66.51 20.62,65.73 20.31,65.42 19.39,65.42 19.25,65.28 19.25,64.9 19.39,64.76 20.26,64.76 20.6,64.42 20.6,63.78 20.05,63.23 20.05,62.8 20.6,62.26 20.6,59.24 21.55,58.28 22.36,58.28 23.55,57.09 23.7,57.09 23.79,57.19 23.94,57.19 24.05,57.08 24.05,56.93 23.95,56.84 23.95,56.69 24.76,55.88 24.91,55.88 25,55.97 v2(25,56.14)
LP3_DQS3_T: length 36.3
  TOP w0.089: U5.D10 25,55.42 v2(25,55.34) ; v2(21.07,72.52) 21.07,75.2 21.96,76.09 22.59,76.09 22.9,75.79 U1.W17
  ART06 w0.089: v2(21.07,72.52) 21.13,72.45 21.13,71.61 20.94,71.41 20.61,71.41 20.1,71.92 19.26,71.92 18.5,71.16 18.5,70.6 18.96,70.14 20.13,70.14 20.28,70 20.28,69.75 20.13,69.61 19.45,69.61 19.11,69.28 19.11,68.75 19.47,68.39 20.15,68.39 20.28,68.27 20.28,67.9 20.15,67.78 19.24,67.78 18.92,67.46 18.92,66.78 19.23,66.46 20.18,66.46 20.28,66.36 20.28,65.87 20.17,65.76 19.25,65.76 18.91,65.42 18.91,64.75 19.25,64.41 20.12,64.41 20.26,64.27 20.26,63.92 19.71,63.38 19.71,62.66 20.26,62.11 20.26,59.09 21.41,57.94 22.22,57.94 24.62,55.54 24.8,55.54 v2(25,55.34)
LP3_ODT: length 43.8
  TOP w0.076: U1.L18 v2(28.57,74.81)
  ART03 w0.076: v2(28.57,74.81) 28.57,74.66 28.9,74.34 28.9,73.97 29.03,73.84 29.75,73.84 33.4,70.18 33.4,70.03 33.27,69.9 32.87,69.9 32.74,69.76 32.74,69.57 32.87,69.44 33.27,69.44 33.4,69.3 33.4,68.64 33.27,68.52 32.89,68.52 32.77,68.39 32.77,68.19 32.89,68.06 33.99,68.06 34.06,67.98 34.06,67.68 33.99,67.6 32.89,67.6 32.77,67.48 32.77,67.27 32.89,67.15 33.63,67.15 33.76,67.02 33.76,66.82 33.63,66.69 32.89,66.69 32.77,66.56 32.77,65.96 32.89,65.84 36.12,65.84 36.25,65.71 36.25,58.19 36.17,58.12 32.23,58.12 31.82,57.71 31.82,54.07 v2(32.15,53.74)
  BOTTOM w0.076: R64.1 30.31,54.14 31.75,54.14 v2(32.15,53.74) 32.51,54.1 34.54,54.1 34.67,54.23 35.18,54.23 35.18,53.09
LP3_VREFCA: length 11.8
  TOP w0.127: U5.H4 27.93,50.86 v2(28.25,50.54) 28.78,50.54 28.91,50.41 28.91,48.9
  TOP w0.254: R69.1 R68.2 C264.1 30.61,46.35 28.91,48.06 28.91,48.9
  BOTTOM w0.254: C266.1 28.45,50.16 28.83,49.78 C265.2
LP3_VREFDQ: length 8.5
  TOP w0.127: U5.J11 28.24,56.87 28.24,57.66
  TOP w0.254: 28.24,57.66 28.24,59.99 C263.1 C92.2 C91.1 R66.1 R67.1
MICBIAS: length 77.3
  TOP w0.254: R31.1 v1(72.01,134.11) ; U1.E3 v2(32.47,85.21)
  TOP w0.305: v3(32,90.6) 49.15,107.75 49.15,119.51 62.36,132.72 v1(62.36,133.48) FB6.1 63.12,134.37 TVS13.1
  ART03 w0.254: v1(62.36,133.48) 65.79,136.91 69.22,136.91 v1(72.01,134.11)
  BOTTOM w0.254: v2(32.47,85.21) 32.47,85.81 C152.1 C153.1 32,88.27 v3(32,90.6)
MICNL: length 5
  TOP w0.102: U1.E2 32.47,85.86 32.47,86.23
  TOP w0.127: 32.47,86.23 32.47,88.1 v3(33.4,89.03)
  BOTTOM w0.127: C154.1 32.89,88.77 33.15,89.03 v3(33.4,89.03)
MICNR: length 15.6
  TOP w0.076: U1.F2 31.83,85.86 31.83,86.49
  TOP w0.127: v3(34.42,90.93) 34.29,90.93 31.83,88.47 31.83,86.49
  BOTTOM w0.127: v3(34.42,90.93) 40.01,96.52 C238.1
MICPL: length 70.5
  TOP w0.127: v1(66.04,124.08) 56.13,124.08 50.67,118.62 50.67,107.19 34.81,91.33 34.81,90.69 34.42,90.3 34.04,90.3 32.15,88.41 U1.E1 ; C157.1 v1(70.94,133.86)
  ART03 w0.127: v1(70.94,133.86) 70.94,128.98 v1(66.04,124.08)
MICPR: length 68.5
  TOP w0.127: v1(64.14,124.84) 56.26,124.84 50.29,118.87 50.29,107.44 31.5,88.65 U1.F1 ; C270.2 v1(67.69,134.37)
  ART03 w0.127: v1(64.14,124.84) 64.14,130.81 v1(67.69,134.37)
MIPI_0V8: length 43.5
  TOP w0.254: U1.R8 v2(25.33,81.96) ; U1.N6 v2(26.63,83.26)
  ART03 w0.254: v2(26.63,83.26) 25.98,83.26
  ART06 w0.254: v2(25.33,81.96) v2(26.63,83.26)
  ART06 w0.305: v1(18.29,36.45) 18.29,32.64 24.13,26.8 24.13,13.34 33.02,4.45
  BOTTOM w0.254: C87.1 26.32,83.57 v2(26.63,83.26) ; v2(25.33,81.96) 24.77,82.52 C86.1 ; C85.1 24.77,84.65 v2(24.68,84.56)
  vias: v1(18.29,38.48) v1(18.29,37.47)
MIPI_0V8_TI: length 41.4
  TOP w0.305: R136.1 14.61,25.91
  ART06 w0.305: v1(15.11,24.89) 14.61,24.38 14.61,13.34 18.29,9.65 v1(18.29,7.87)
  BOTTOM w0.254: 35.56,4.45 34.16,3.05 19.56,3.05 19.05,3.56 19.05,7.11 v1(18.29,7.87)
MIPI_1V8: length 111.9
  TOP w0.254: U1.N7 v2(26.63,82.61) ; U1.R9 v2(25.33,81.31)
  TOP w0.381: v1(42.16,41.02) 43.43,42.29 60.45,42.29 62.23,44.07 68.07,44.07 v1(69.98,45.97)
  ART06 w0.254: 20.32,1.91 19.05,3.17 19.05,6.22 13.21,12.06 13.21,38.23 v1(16.76,41.78) ; v2(26.63,82.61) v2(25.33,81.31)
  BOTTOM w0.254: v2(19.58,76.71) C88.1 ; v2(26.63,82.61) 26.09,82.61 C90.1
  BOTTOM w0.381: v1(16.76,41.78) 18.29,40.26 41.4,40.26 v1(42.16,41.02) ; R223.2 76.2,45.97 v1(69.98,45.97)
  vias: v1(16.76,43.81) v1(16.76,42.8)
MIPI_1V8_TI: length 39.4
  TOP w0.305: R161.2 14.61,38.35
  ART06 w0.254: 22.86,1.91 21.59,3.17 21.59,10.03 16,15.62 16,36.58 v1(15.24,37.34)
MIPI_RX0_CLK_N: length 88.9
  TOP w0.114: U1.Y2 22.38,85.52 22.1,85.52 20.74,86.88 20.74,87.88 20.55,88.07 20.55,88.33 20.74,88.52 20.74,89.65 18.53,91.86 18.53,95.68 13.5,100.71 13.5,115.68 13.93,116.11 15.48,116.11 15.66,116.28 15.66,116.55 15.41,116.79 13.88,116.79 13.5,117.17 13.5,125.36 16.49,128.36 17.79,128.36 17.99,128.56 17.99,129.9 18.39,130.3 18.96,130.3 19.36,129.9 19.36,128.56 19.56,128.36 20.02,128.36 20.22,128.56 20.22,129.9 20.62,130.3 21.19,130.3 21.59,129.9 21.59,128.56 21.79,128.36 22.08,128.36 22.28,128.56 22.28,129.9 22.68,130.3 23.25,130.3 23.65,129.9 23.65,128.56 23.85,128.36 24.14,128.36 24.34,128.56 24.34,129.9 24.74,130.3 25.31,130.3 25.71,129.9 25.71,128.56 25.91,128.36 26.19,128.36 26.39,128.56 26.39,129.9 26.8,130.3 27.36,130.3 27.77,129.9 27.77,128.56 27.97,128.36 28.25,128.36 28.45,128.56 28.45,129.9 28.85,130.3 29.42,130.3 29.82,129.9 29.82,128.56 30.02,128.36 32.62,128.36 32.84,128.58 32.84,129.21 32.75,129.3 J3.1
MIPI_RX0_CLK_P: length 89
  TOP w0.114: J3.3 33.25,129.26 33.19,129.2 33.19,128.44 32.77,128.02 29.88,128.02 29.48,128.42 29.48,129.76 29.28,129.96 29,129.96 28.79,129.76 28.79,128.42 28.39,128.02 27.82,128.02 27.42,128.42 27.42,129.76 27.22,129.96 26.94,129.96 26.74,129.76 26.74,128.42 26.34,128.02 25.77,128.02 25.37,128.42 25.37,129.76 25.16,129.96 24.88,129.96 24.68,129.76 24.68,128.42 24.28,128.02 23.71,128.02 23.31,128.42 23.31,129.76 23.11,129.96 22.82,129.96 22.62,129.76 22.62,128.42 22.22,128.02 21.65,128.02 21.25,128.42 21.25,129.76 21.05,129.96 20.77,129.96 20.56,129.76 20.56,128.42 20.16,128.02 19.42,128.02 19.02,128.42 19.02,129.76 18.82,129.96 18.53,129.96 18.33,129.76 18.33,128.42 17.93,128.02 16.64,128.02 13.84,125.22 13.84,117.31 14.02,117.14 15.56,117.14 16,116.69 16,116.14 15.63,115.76 14.07,115.76 13.84,115.54 13.84,100.85 18.87,95.82 18.87,92 21.08,89.79 21.08,87.02 22.24,85.86 22.72,85.86 U1.W2
MIPI_RX0_D0_N: length 88.9
  TOP w0.114: U1.W3 22.72,85.21 21.67,85.21 19.23,87.66 19.23,87.94 19.9,88.62 19.9,89.19 19.5,89.59 18.93,89.59 18.26,88.91 17.97,88.91 16.51,90.38 16.51,90.93 17.78,92.2 17.78,95.36 12.66,100.48 12.66,125.69 18.07,131.1 18.93,131.1 19.33,131.5 19.33,132.3 19.53,132.5 19.82,132.5 20.02,132.3 20.02,131.5 20.42,131.1 23.34,131.1 23.74,131.5 23.74,132.43 23.94,132.63 24.22,132.63 24.42,132.43 24.42,131.5 24.83,131.1 25.39,131.1 25.8,131.5 25.8,132.43 26,132.63 26.28,132.63 26.48,132.43 26.48,131.5 26.88,131.1 27.45,131.1 27.85,131.5 27.85,132.43 28.05,132.63 28.34,132.63 28.54,132.43 28.54,131.5 28.94,131.1 29.51,131.1 29.91,131.5 29.91,132.43 30.11,132.63 30.4,132.63 30.6,132.43 30.6,129.69 31,129.29 31.57,129.29 31.97,129.69 31.97,131.03 33.25,132.31 J3.4
MIPI_RX0_D0_P: length 88.9
  TOP w0.114: J3.2 32.75,133.24 32.91,133.08 32.91,132.46 32.57,132.11 32.29,132.11 32.1,131.93 32.1,131.65 31.63,131.17 31.63,129.83 31.42,129.63 31.14,129.63 30.94,129.83 30.94,132.57 30.54,132.97 29.97,132.97 29.57,132.57 29.57,131.65 29.37,131.44 29.08,131.44 28.88,131.65 28.88,132.57 28.48,132.97 27.91,132.97 27.51,132.57 27.51,131.65 27.31,131.44 27.03,131.44 26.82,131.65 26.82,132.57 26.42,132.97 25.85,132.97 25.45,132.57 25.45,131.65 25.25,131.44 24.97,131.44 24.77,131.65 24.77,132.57 24.37,132.97 23.8,132.97 23.4,132.57 23.4,131.65 23.2,131.44 20.56,131.44 20.36,131.65 20.36,132.44 19.96,132.84 19.39,132.84 18.99,132.44 18.99,131.65 18.79,131.44 17.93,131.44 12.32,125.83 12.32,100.34 17.44,95.22 17.44,92.34 16.17,91.07 16.17,90.23 17.83,88.57 18.4,88.57 19.08,89.25 19.36,89.25 19.56,89.05 19.56,88.76 18.88,88.09 18.88,87.52 21.53,84.87 22.38,84.87 U1.Y3
MIPI_RX0_D1_N: length 88.8
  TOP w0.114: U1.V1 23.72,86.2 23.72,86.76 22.19,88.29 22.19,88.69 22.32,88.82 22.55,88.82 22.68,88.96 22.68,89.15 22.55,89.28 22.32,89.28 22.19,89.42 22.19,90.21 19.96,92.43 19.96,96.28 14.99,101.26 14.99,108.29 15.19,108.49 16.24,108.49 16.64,108.89 16.64,109.46 16.24,109.86 15.19,109.86 14.99,110.06 14.99,110.35 15.19,110.55 18.27,110.55 18.67,110.95 18.67,111.52 18.27,111.92 15.19,111.92 14.99,112.12 14.99,112.41 15.19,112.61 19.28,112.61 19.68,113.01 19.68,113.58 19.28,113.98 15.19,113.98 14.99,114.18 14.99,114.46 15.19,114.66 17.89,114.66 18.41,115.19 18.41,115.91 14.99,119.34 14.99,124.71 17.18,126.91 34.05,126.91 34.67,127.53 34.67,129.16 34.75,129.24 J3.9
MIPI_RX0_D1_P: length 88.9
  TOP w0.114: J3.7 34.25,129.24 34.33,129.16 34.33,127.68 33.91,127.25 17.04,127.25 14.64,124.86 14.64,119.2 18.07,115.77 18.07,115.33 17.75,115.01 15.04,115.01 14.64,114.61 14.64,114.04 15.04,113.64 19.14,113.64 19.34,113.43 19.34,113.15 19.14,112.95 15.04,112.95 14.64,112.55 14.64,111.98 15.04,111.58 18.13,111.58 18.33,111.38 18.33,111.09 18.13,110.89 15.04,110.89 14.64,110.49 14.64,109.92 15.04,109.52 16.09,109.52 16.29,109.32 16.29,109.04 16.09,108.84 15.04,108.84 14.64,108.43 14.64,101.11 19.62,96.14 19.62,92.29 21.84,90.07 21.84,88.14 23.37,86.61 23.37,85.86 U1.V2
MIPI_RX1_CLK_N: length 88.8
  TOP w0.114: U1.W5 22.72,83.91 20.46,83.91 14.62,89.75 13.25,89.75 10.34,92.66 10.34,126.73 18.94,135.33 19.35,135.33 19.84,134.84 20.41,134.84 20.81,135.24 20.81,135.81 20.32,136.3 20.32,136.58 20.55,136.82 21.46,136.82 21.66,136.62 21.66,135.15 22.06,134.75 22.63,134.75 23.03,135.15 23.03,136.62 23.23,136.82 32.68,136.82 32.82,136.68 32.82,136.53 32.95,136.4 33.14,136.4 33.27,136.53 33.27,136.68 33.41,136.82 33.6,136.82 33.73,136.68 33.73,136.53 33.86,136.4 34.05,136.4 34.19,136.53 34.19,136.68 34.32,136.82 34.66,136.82 35.83,135.64 35.83,134.97 35.75,134.89 J3.14
MIPI_RX1_CLK_P: length 88.7
  TOP w0.114: U1.Y5 22.38,83.57 20.32,83.57 14.48,89.41 13.1,89.41 9.99,92.52 9.99,126.87 18.8,135.67 19.49,135.67 19.98,135.18 20.27,135.18 20.47,135.38 20.47,135.66 19.98,136.16 19.98,136.73 20.41,137.16 21.6,137.16 22,136.76 22,135.29 22.2,135.09 22.48,135.09 22.68,135.29 22.68,136.76 23.09,137.16 34.8,137.16 36.18,135.78 36.18,134.97 36.25,134.89 J3.16
MIPI_RX1_D2_N: length 88.9
  TOP w0.114: J3.10 34.75,134.89 34.67,134.97 34.67,135.32 34.36,135.64 30.72,135.64 30.26,135.18 30.26,134.25 30.08,134.07 29.6,134.07 29.4,134.27 29.4,135.49 29,135.89 28.43,135.89 28.03,135.49 28.03,134.27 27.83,134.07 27.55,134.07 27.35,134.27 27.35,135.49 26.94,135.89 26.38,135.89 25.97,135.49 25.97,134.27 25.77,134.07 25.49,134.07 25.29,134.27 25.29,135.49 24.89,135.89 24.32,135.89 23.92,135.49 23.92,134.27 23.72,134.07 22.65,134.07 22.25,133.67 22.25,132.75 22.05,132.55 21.77,132.55 21.56,132.75 21.56,133.67 21.16,134.07 18.94,134.07 11.09,126.22 11.09,92.98 13.35,90.72 14.39,90.72 20.88,84.22 22.38,84.22 U1.Y4
MIPI_RX1_D2_P: length 88.8
  TOP w0.114: U1.W4 22.72,84.56 21.03,84.56 14.53,91.06 13.49,91.06 11.43,93.12 11.43,126.08 19.08,133.73 21.02,133.73 21.22,133.53 21.22,132.61 21.62,132.21 22.19,132.21 22.59,132.61 22.59,133.53 22.79,133.73 23.86,133.73 24.26,134.13 24.26,135.35 24.46,135.55 24.74,135.55 24.95,135.35 24.95,134.13 25.35,133.73 25.92,133.73 26.32,134.13 26.32,135.35 26.52,135.55 26.8,135.55 27,135.35 27,134.13 27.4,133.73 27.97,133.73 28.37,134.13 28.37,135.35 28.58,135.55 28.86,135.55 29.06,135.35 29.06,134.13 29.46,133.73 30.23,133.73 30.61,134.11 30.61,135.04 30.86,135.29 31.26,135.29 31.4,135.16 31.4,134.86 31.53,134.72 31.72,134.72 31.85,134.86 31.85,135.16 31.99,135.29 34.22,135.29 34.33,135.18 34.33,134.97 34.25,134.89 J3.8
MIPI_RX1_D3_N: length 89.1
  TOP w0.114: U1.W6 22.72,83.26 19.86,83.26 14.48,88.65 12.8,88.65 9.23,92.21 9.23,127.11 20.08,137.96 35.65,137.96 36.57,137.03 36.57,136.85 36.38,136.65 36.38,136.46 36.52,136.33 36.71,136.33 36.9,136.52 37.09,136.52 37.41,136.2 37.41,135.05 37.25,134.89 J3.20
MIPI_RX1_D3_P: length 89.2
  TOP w0.114: U1.Y6 22.38,82.92 19.72,82.92 14.34,88.3 12.66,88.3 8.89,92.07 8.89,127.26 19.94,138.3 35.79,138.3 37.75,136.34 J3.22
MIPI_RX2_CLK_N: length 88.7
  TOP w0.114: U1.R2 25.32,85.86 25.32,91.64 23.24,93.73 23.24,97.17 22.01,98.4 22.01,101.97 21.83,102.15 18.35,102.15 18.03,102.46 18.03,105.92 21.01,108.9 21.58,108.9 22.18,108.29 22.47,108.29 22.67,108.5 22.67,108.78 22.07,109.38 22.07,109.95 23.37,111.25 23.37,115.21 18.03,120.55 18.03,123.29 18.53,123.79 33.57,123.79 34.16,123.19 34.16,119.89 34.42,119.63 40.16,119.63 41.99,121.46 41.99,126.06 40.41,127.64 39.62,127.64 38.83,128.43 38.83,129.16 38.75,129.24 J3.25
MIPI_RX2_CLK_P: length 88.8
  TOP w0.114: J3.27 39.25,129.24 39.18,129.16 39.18,128.57 39.77,127.98 40.55,127.98 42.33,126.2 42.33,121.32 40.3,119.29 34.27,119.29 33.82,119.75 33.82,123.05 33.42,123.44 18.67,123.44 18.38,123.15 18.38,120.69 23.71,115.35 23.71,111.11 22.41,109.81 22.41,109.52 23.01,108.92 23.01,108.35 22.61,107.95 22.04,107.95 21.44,108.55 21.15,108.55 18.38,105.78 18.38,102.6 18.49,102.49 21.97,102.49 22.35,102.11 22.35,98.54 23.58,97.31 23.58,93.87 23.94,93.51 24.13,93.51 24.2,93.59 24.39,93.59 24.53,93.46 24.53,93.27 24.45,93.19 24.45,93 24.58,92.87 24.77,92.87 24.85,92.94 25.04,92.94 25.17,92.81 25.17,92.62 25.1,92.54 25.1,92.35 25.67,91.79 25.67,86.2 U1.R1
MIPI_RX2_D4_N: length 88.8
  TOP w0.114: J3.21 37.75,129.24 37.68,129.17 37.68,128.44 39.28,126.83 40.15,126.83 41.24,125.75 41.24,121.75 39.88,120.4 35.43,120.4 34.96,120.87 34.96,124.44 34.82,124.59 18.16,124.59 17.27,123.7 17.27,120.24 22.61,114.91 22.61,113.99 21.97,113.36 21.97,112.98 22.61,112.34 22.61,111.63 17.27,106.3 17.27,102.07 18.97,100.37 19.26,100.37 20.19,101.31 20.75,101.31 21.16,100.9 21.16,100.33 20.23,99.4 20.23,99.12 22.15,97.2 22.15,93.53 23.53,92.15 23.72,92.15 23.77,92.2 23.96,92.2 24.09,92.06 24.09,91.88 24.04,91.82 24.04,91.64 24.17,91.5 24.36,91.5 24.41,91.55 24.6,91.55 24.74,91.42 24.74,91.23 24.69,91.18 24.69,90.99 25.02,90.66 25.02,86.2 U1.T1
MIPI_RX2_D4_P: length 88.8
  TOP w0.114: U1.T2 24.67,85.86 24.67,90.52 21.81,93.38 21.81,97.05 19.88,98.98 19.88,99.54 20.82,100.47 20.82,100.76 20.61,100.97 20.34,100.97 19.4,100.03 18.83,100.03 16.93,101.93 16.93,106.44 22.26,111.78 22.26,112.2 21.63,112.84 21.63,113.5 22.26,114.13 22.26,114.77 16.93,120.1 16.93,123.84 18.02,124.93 34.96,124.93 35.31,124.59 35.31,121.01 35.58,120.74 39.74,120.74 40.89,121.9 40.89,125.6 40.01,126.49 39.14,126.49 37.34,128.29 37.34,129.16 37.25,129.24 J3.19
MIPI_RX2_D5_N: length 88.7
  TOP w0.114: J3.13 35.75,129.24 35.83,129.16 35.83,128.15 39.75,124.23 39.75,122.53 39.23,122.01 36.74,122.01 36.58,122.17 36.58,122.68 36.78,122.88 38.33,122.88 38.73,123.28 38.73,123.85 38.33,124.25 36.78,124.25 36.58,124.45 36.58,126.09 35.83,126.83 35.14,126.83 34.42,126.11 17.55,126.11 15.79,124.35 15.79,119.7 20.45,115.04 20.45,111.61 15.79,106.95 15.79,101.52 20.71,96.59 20.71,92.85 23.39,90.17 23.39,88.11 24.02,87.48 24.02,85.86 U1.U2
MIPI_RX2_D5_P: length 88.8
  TOP w0.114: U1.U1 24.37,86.2 24.37,87.62 23.74,88.25 23.74,88.67 23.87,88.8 23.97,88.8 24.1,88.94 24.1,89.13 23.97,89.26 23.87,89.26 23.74,89.4 23.74,89.58 23.87,89.72 23.97,89.72 24.1,89.85 24.1,90.04 23.97,90.18 23.87,90.18 21.06,92.99 21.06,96.74 16.13,101.66 16.13,106.81 20.79,111.47 20.79,115.18 16.13,119.84 16.13,124.21 17.69,125.77 34.56,125.77 35.28,126.49 35.69,126.49 36.23,125.95 36.23,124.31 36.63,123.91 38.19,123.91 38.39,123.71 38.39,123.42 38.19,123.22 36.63,123.22 36.23,122.82 36.23,122.03 36.6,121.67 39.37,121.67 40.09,122.39 40.09,124.37 36.18,128.29 36.18,129.16 36.25,129.24 J3.15
MIPI_TX0_CLK_N: length 38.9
  TOP w0.114: J4.19 7.18,97.91 7.1,97.99 6.29,97.99 6.17,97.87 v3(6.17,97.65) ; v3(15.07,84.33) 14.68,84.33 14.57,84.21 14.57,83.99 15.75,82.8 16.38,82.8 17.88,81.31 22.72,81.31 U1.W9
  BOTTOM w0.114: v3(6.17,97.65) 6.53,98.01 9.82,98.01 10.16,97.66 10.16,97.04 9.96,96.84 8.53,96.84 8.13,96.43 8.13,95.87 8.53,95.46 9.96,95.46 10.16,95.26 10.16,93.47 15.88,87.76 15.88,85.68 15.74,85.55 15.5,85.55 15.37,85.41 15.37,85.22 15.5,85.09 15.74,85.09 15.88,84.96 15.88,84.22 15.37,83.72 14.86,83.72 14.64,83.94 14.64,84.1 14.86,84.33 v3(15.07,84.33)
MIPI_TX0_CLK_P: length 38.9
  TOP w0.114: J4.20 7.18,98.41 7.1,98.33 6.51,98.33 v3(6.17,98.67) ; v3(14.18,84.33) 14.22,84.28 14.22,83.84 15.61,82.46 16.24,82.46 17.73,80.97 22.38,80.97 U1.Y9
  BOTTOM w0.114: v3(6.17,98.67) 6.49,98.35 9.96,98.35 10.5,97.81 10.5,96.9 10.1,96.49 8.67,96.49 8.47,96.29 8.47,96.01 8.67,95.81 10.1,95.81 10.5,95.41 10.5,93.61 16.22,87.9 16.22,84.08 15.51,83.37 14.72,83.37 14.29,83.8 14.29,84.21 v3(14.18,84.33)
MIPI_TX0_D0_N: length 39
  TOP w0.114: v3(12.15,84.33) 12.32,84.33 12.46,84.19 12.46,82.94 14.21,81.19 16.37,81.19 17.24,80.32 22.38,80.32 U1.Y10 ; v3(2.74,99.24) 2.74,99.45 2.85,99.57 7.02,99.57 7.18,99.41 J4.22
  BOTTOM w0.114: v3(2.74,99.24) 2.74,99.58 2.85,99.69 3.32,99.69 3.98,99.04 3.98,94.32 5.52,92.77 5.52,90.64 6.21,89.95 6.69,89.95 11.52,85.13 12.05,85.13 12.45,84.73 12.45,84.44 12.33,84.33 v3(12.15,84.33)
MIPI_TX0_D0_P: length 39.1
  TOP w0.114: J4.23 3.09,99.91 v3(2.74,100.26) ; U1.W10 22.72,80.66 17.38,80.66 16.51,81.53 14.35,81.53 12.8,83.08 12.8,84.09 v3(13.04,84.33)
  BOTTOM w0.114: v3(13.04,84.33) 12.79,84.58 12.79,84.87 12.19,85.47 11.66,85.47 6.84,90.3 6.35,90.3 5.87,90.78 5.87,92.92 4.32,94.47 4.32,99.19 3.47,100.04 2.96,100.04 v3(2.74,100.26)
MIPI_TX0_D1_N: length 39
  TOP w0.114: v3(3.25,96.26) 3.48,96.49 7.13,96.49 7.2,96.41 J4.16 ; v3(11,84.33) 10.88,84.33 10.77,84.21 10.77,83.21 13.97,80.01 22.72,80.01 U1.W11
  BOTTOM w0.114: v3(3.25,96.26) 3.25,96.44 3.13,96.56 2.58,96.56 2.41,96.39 2.41,94.72 4.78,92.36 4.78,89.97 6.16,88.58 6.16,88.01 5.69,87.54 5.69,87.25 5.89,87.05 6.17,87.05 6.65,87.53 8.11,87.53 10.67,84.96 10.67,84.46 10.8,84.33 v3(11,84.33)
MIPI_TX0_D1_P: length 39.1
  TOP w0.114: J4.17 7.2,96.91 7.13,96.83 3.56,96.83 v3(3.25,97.15) ; v3(10.12,84.33) 10.43,84.02 10.43,83.07 13.83,79.67 22.38,79.67 U1.Y11
  BOTTOM w0.114: v3(3.25,97.15) 3,96.9 2.44,96.9 2.07,96.54 2.07,94.58 4.43,92.21 4.43,89.82 5.82,88.44 5.82,88.15 5.34,87.68 5.34,87.11 5.75,86.71 6.32,86.71 6.79,87.18 7.96,87.18 10.33,84.82 10.33,84.54 v3(10.12,84.33)
MIPI_TX1_D2_N: length 39
  TOP w0.114: U1.Y8 22.38,81.62 18.46,81.62 14.8,85.28 8.83,85.28 8.25,85.86 8.25,86.43 8.85,87.03 8.85,87.31 8.64,87.52 8.36,87.52 7.76,86.92 7.19,86.92 5.84,88.27 3.87,88.27 3.76,88.15 v3(3.76,87.91) ; v3(2.16,92.16) 2.16,92.27 2.27,92.38 2.69,92.38 5.38,95.07 5.76,95.07 5.96,94.87 6.22,94.87 6.42,95.07 7.05,95.07 7.2,94.91 J4.13
  BOTTOM w0.114: v3(3.76,87.91) 3.76,88.15 3.64,88.27 1.93,88.27 1.52,88.67 1.52,89.24 1.93,89.64 2.5,89.64 2.71,89.84 2.71,92.25 2.58,92.38 2.26,92.38 2.16,92.28 v3(2.16,92.16)
MIPI_TX1_D2_P: length 38.9
  TOP w0.114: J4.14 5.24,95.41 2.55,92.72 2.36,92.72 v3(2.16,92.92) ; v3(3.76,88.8) 3.95,88.61 5.98,88.61 7.33,87.26 7.62,87.26 8.22,87.86 8.79,87.86 9.19,87.46 9.19,86.89 8.59,86.29 8.59,86 8.97,85.62 14.94,85.62 18.6,81.96 22.72,81.96 U1.W8
  BOTTOM w0.114: v3(3.76,88.8) 3.56,88.61 2.07,88.61 1.87,88.81 1.87,89.09 2.07,89.29 2.65,89.29 3.05,89.7 3.05,92.4 2.72,92.72 2.36,92.72 v3(2.16,92.92)
MIPI_TX1_D3_N: length 38.8
  TOP w0.114: J4.25 7.18,100.91 7.1,100.99 6.51,100.99 v3(6.17,100.65) ; v3(12.7,87.33) 13.15,86.88 14.97,86.88 19.24,82.61 22.72,82.61 U1.W7
  BOTTOM w0.114: v3(6.17,100.65) 6.17,100.98 6.06,101.09 5.78,101.09 5.56,100.87 5.56,94.87 6.84,93.6 8.26,93.6 8.81,93.05 8.81,92.48 7.76,91.43 7.76,91.15 7.96,90.95 8.25,90.95 9.29,91.99 9.86,91.99 11.94,89.92 11.94,89.28 11.54,88.87 10.83,88.87 10.63,88.67 10.63,88.39 10.83,88.19 11.54,88.19 11.94,87.79 11.94,87.25 12.06,87.12 12.49,87.12 v3(12.7,87.33)
MIPI_TX1_D3_P: length 38.8
  TOP w0.114: v3(6.17,101.67) 6.51,101.33 7.1,101.33 7.18,101.41 J4.26 ; U1.Y7 22.38,82.27 19.1,82.27 14.83,86.54 12.92,86.54 v3(12.7,86.32)
  BOTTOM w0.114: v3(6.17,101.67) 5.94,101.43 5.64,101.43 5.22,101.01 5.22,94.73 6.69,93.26 8.11,93.26 8.46,92.9 8.46,92.62 7.42,91.57 7.42,91.01 7.82,90.6 8.39,90.6 9.44,91.65 9.72,91.65 11.6,89.77 11.6,89.42 11.39,89.22 10.69,89.22 10.29,88.82 10.29,88.25 10.69,87.85 11.39,87.85 11.6,87.64 11.6,87.11 11.92,86.78 12.24,86.78 v3(12.7,86.32)
MMC1_CLK: length 65.3
  TOP w0.127: R122.1 29.97,100.08 v1(31.37,100.08) ; v1(68.07,85.22) 67.2,86.09 U4.5
  ART06 w0.127: v1(31.37,100.08) 33.04,98.4 33.04,97.56 33.19,97.41 33.4,97.41 33.55,97.56 33.55,98.4 33.7,98.55 33.91,98.55 34.06,98.4 34.06,97.56 34.21,97.41 34.42,97.41 34.57,97.56 34.57,98.4 34.71,98.55 34.92,98.55 35.07,98.4 35.07,97.56 35.22,97.41 35.43,97.41 35.58,97.56 35.58,98.4 35.73,98.55 35.94,98.55 36.09,98.4 36.09,97.56 36.24,97.41 36.45,97.41 36.6,97.56 36.6,98.4 36.75,98.55 36.96,98.55 37.11,98.4 37.11,97.56 37.25,97.41 37.47,97.41 37.61,97.56 37.61,98.4 37.76,98.55 38.07,98.55 38.22,98.4 38.22,97.43 38.37,97.28 38.58,97.28 38.73,97.43 38.73,98.4 38.87,98.55 39.09,98.55 39.23,98.4 39.23,97.43 39.38,97.28 39.59,97.28 39.74,97.43 39.74,98.4 39.89,98.55 42.16,98.55 48.39,92.33 57.4,92.33 59.82,89.92 63.75,89.92 68.07,85.6 v1(68.07,85.22)
  BOTTOM w0.127: U22.3 v1(68.07,85.22) 68.2,85.09 R188.2
MMC1_CMD: length 64.6
  TOP w0.127: v1(68.2,87.63) 67.54,88.29 U4.3 ; R121.1 32.26,100.08 v1(32.64,100.08)
  ART06 w0.127: v1(68.2,87.63) 66.8,87.63 63.27,91.16 62.97,91.16 62.82,91.01 62.82,90.57 62.67,90.42 62.46,90.42 62.31,90.57 62.31,91.01 62.17,91.16 61.95,91.16 61.81,91.01 61.81,90.57 61.66,90.42 61.45,90.42 61.3,90.57 61.3,91.01 61.15,91.16 60.94,91.16 60.79,91.01 60.79,90.57 60.64,90.42 60.43,90.42 60.28,90.57 60.28,91.01 60.13,91.16 59.33,91.16 57.66,92.84 50.42,92.84 50.14,93.11 49.93,93.11 49.76,92.94 49.55,92.94 49.4,93.09 49.4,93.3 49.57,93.47 49.57,93.68 49.35,93.9 49.14,93.9 48.59,93.35 48.38,93.35 48.23,93.5 48.23,93.71 48.78,94.26 48.78,94.47 48.63,94.62 48.42,94.62 47.87,94.07 47.66,94.07 47.51,94.22 47.51,94.43 48.06,94.98 48.06,95.19 47.92,95.34 47.71,95.34 47.15,94.79 46.94,94.79 46.79,94.94 46.79,95.15 47.35,95.7 47.35,95.91 47.2,96.06 46.99,96.06 46.43,95.51 46.22,95.51 46.08,95.66 46.08,95.87 46.63,96.42 46.63,96.63 46.48,96.78 46.27,96.78 45.72,96.23 45.51,96.23 45.36,96.38 45.36,96.59 45.91,97.14 45.91,97.35 45.76,97.5 45.55,97.5 45,96.95 44.79,96.95 44.64,97.09 44.64,97.3 45.19,97.86 45.19,98.07 45.04,98.22 44.83,98.22 44.28,97.66 44.07,97.66 43.92,97.81 43.92,98.02 44.47,98.58 44.47,98.79 44.2,99.06 33.66,99.06 v1(32.64,100.08)
  BOTTOM w0.127: U22.2 68.07,87.5 v1(68.2,87.63) R162.2
